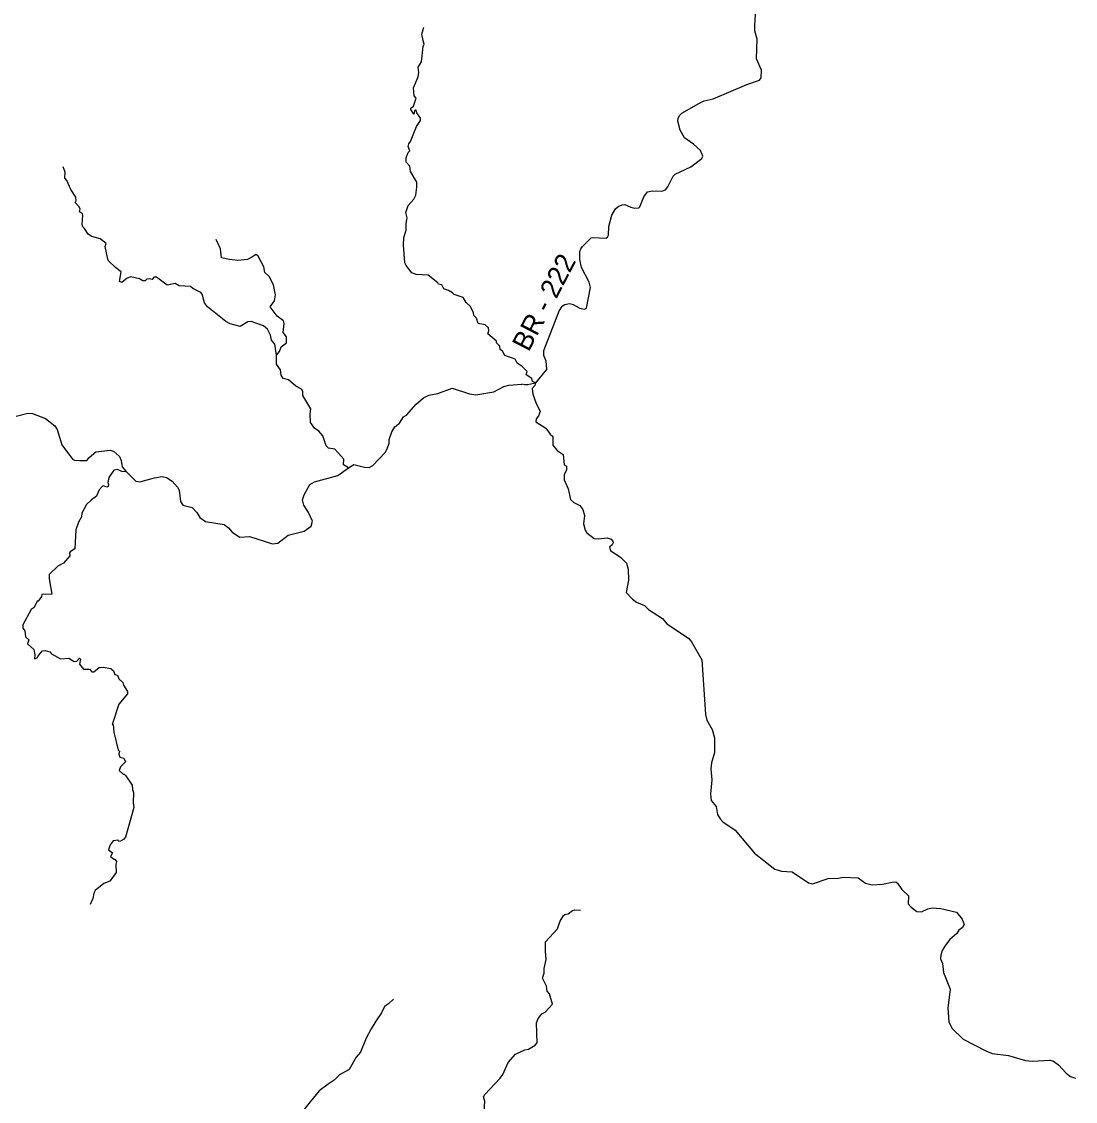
# Model space of a CAD drawing. Extents: x 332 to 501, y 9447 to 9559.
# Drawn here: x 378.21 to 398.6, y 9525.86 to 9546.74 of the extents above; entities that cross this region are included whole.
import ezdxf

# ---------------------------------------------------------------- set-up
doc = ezdxf.new("R2010")
doc.units = 0
for name, color, linetype in [('Level 2', 7, 'Continuous'), ('Level 31', 7, 'Continuous'), ('Level 5', 7, 'Continuous'), ('Level 6', 7, 'Continuous'), ('Level 7', 7, 'Continuous')]:
    doc.layers.add(name, color=color, linetype=linetype)

msp = doc.modelspace()

# ---------------------------------------------------------------- linework, layer by layer
at = {"layer": 'Level 2'}
for points in [[(389.0092, 9541.194), (389.1024, 9541.175), (389.1431, 9541.1966), (389.2215, 9541.5947), (389.1959, 9541.7003), (389.044, 9541.9801), (389.0152, 9542.1384), (389.0152, 9542.2919), (389.0296, 9542.3431), (389.0648, 9542.3878), (389.2311, 9542.5541), (389.2711, 9542.5637), (389.5148, 9542.5497), (389.5486, 9542.5649), (389.5683, 9542.6033), (389.5774, 9542.7724), (389.6301, 9542.9943), (389.7012, 9543.117), (389.7571, 9543.1633), (389.8307, 9543.1953), (389.8851, 9543.2001), (389.997, 9543.1457), (390.0769, 9543.1265), (390.1553, 9543.1345), (390.1761, 9543.1521), (390.2519, 9543.3458), (390.32, 9543.4431), (390.4127, 9543.4623), (390.6014, 9543.4543), (390.6676, 9543.4853), (390.7128, 9543.5383), (390.8204, 9543.7502), (390.8572, 9543.7885), (391.161, 9543.9276), (391.3705, 9544.0907), (391.3913, 9544.1371), (391.3481, 9544.2426), (391.2122, 9544.3689), (391.0411, 9544.4889), (390.9516, 9544.6392), (390.9084, 9544.8119), (390.9148, 9544.8694), (390.95, 9544.927), (390.9835, 9544.9638), (391.3145, 9545.1556), (391.4217, 9545.202), (391.5928, 9545.242), (392.2451, 9545.5186), (392.4866, 9545.6034), (392.5217, 9545.6481), (392.5249, 9545.8), (392.4306, 9546.0175), (392.4466, 9546.3981), (392.3999, 9546.5581), (392.3975, 9546.6618), (392.4258, 9547.076)], [(389.0092, 9541.194), (388.8937, 9541.2594), (388.8106, 9541.2767), (388.7205, 9541.2594), (388.6616, 9541.2178), (388.6131, 9541.152), (388.3117, 9540.3725), (388.3117, 9540.2859), (388.3568, 9540.1733), (388.3706, 9540.0104), (388.1558, 9539.7504)], [(384.5385, 9538.1042), (384.6403, 9538.1748), (384.846, 9538.1203), (384.9367, 9538.1143), (385.0093, 9538.1506), (385.2452, 9538.4048), (385.2876, 9538.4775), (385.3239, 9538.5864), (385.3239, 9538.653), (385.3783, 9538.8044), (385.4371, 9538.8988), (385.5218, 9538.9714), (385.6004, 9539.0925), (385.6609, 9539.1288), (385.8485, 9539.3407), (385.9876, 9539.4618), (386.0905, 9539.5102), (386.2659, 9539.5465), (386.5442, 9539.6494), (386.8769, 9539.5405), (387.004, 9539.5162), (387.3525, 9539.5768), (387.5401, 9539.6797), (387.6369, 9539.7039), (387.891, 9539.7221)], [(387.9483, 9539.7141), (387.891, 9539.7221)], [(388.0064, 9539.7127), (387.9483, 9539.7141)], [(388.1253, 9539.7402), (388.0064, 9539.7127)], [(388.1558, 9539.7504), (388.1253, 9539.7402)], [(378.1074, 9539.1058), (378.3373, 9539.1664), (378.422, 9539.1603), (378.6761, 9539.0635), (378.8552, 9538.9182), (378.9036, 9538.8516), (378.9944, 9538.555), (379.2001, 9538.2765), (379.2364, 9538.2583), (379.3392, 9538.2462), (379.4784, 9538.2462), (379.5207, 9538.3068), (379.6478, 9538.4157), (379.9261, 9538.446), (379.9926, 9538.4278), (380.1076, 9538.3249), (380.1378, 9538.2523), (380.156, 9538.1252), (380.2286, 9538.0404)], [(380.2286, 9538.0404), (380.4222, 9537.8528), (380.5008, 9537.8346), (380.7851, 9537.9133), (380.9303, 9537.9375), (381.015, 9537.9194), (381.1239, 9537.8467)], [(383.3727, 9536.8067), (383.6813, 9536.8854), (383.8144, 9536.9762), (383.8386, 9537.0731), (383.766, 9537.2426), (383.6723, 9537.3879), (383.6481, 9537.4908), (383.6783, 9537.5876), (383.7872, 9537.7874), (383.878, 9537.8358), (384.3317, 9537.9569), (384.5385, 9538.1042)], [(381.1239, 9537.8467), (381.2328, 9537.7317), (381.2631, 9537.6772), (381.2873, 9537.4532), (381.3357, 9537.3867), (381.5111, 9537.3382), (381.6019, 9537.2414), (381.6624, 9537.1445), (381.7713, 9537.0719), (382.1325, 9537.0126), (382.2172, 9536.946), (382.2898, 9536.8612), (382.435, 9536.7644), (382.6225, 9536.7765), (383.0702, 9536.6372), (383.1731, 9536.6493), (383.3727, 9536.8067)]]:
    msp.add_lwpolyline(points, dxfattribs=at)
at = {"layer": 'Level 5'}
for points in [[(386.0014, 9546.3018), (385.9838, 9546.3737), (385.9537, 9546.4941), (385.9938, 9546.6295)], [(385.6474, 9543.0433), (385.6908, 9543.1777), (385.8014, 9543.3041), (385.8409, 9543.3792), (385.8567, 9543.5333), (385.8567, 9543.6309), (385.7343, 9543.8364), (385.7224, 9543.9391), (385.6513, 9544.0182), (385.6553, 9544.1051), (385.6948, 9544.2039), (385.7224, 9544.2355), (385.6948, 9544.3224), (385.7027, 9544.3698), (385.7382, 9544.4197), (385.8527, 9544.7081), (385.9317, 9544.8267), (385.9278, 9544.8701), (385.8606, 9544.9689), (385.8448, 9545.0203), (385.833, 9545.0321), (385.8132, 9545.0084), (385.8014, 9544.9452), (385.7461, 9545.0361), (385.7461, 9545.0598), (385.7935, 9545.0993), (385.8448, 9545.2534), (385.8093, 9545.3008), (385.7974, 9545.4538), (385.8843, 9545.6711), (385.8962, 9545.7541), (385.8883, 9545.8529), (385.9475, 9545.9556), (385.9843, 9546.2575), (386.0014, 9546.3018)], [(379.3441, 9543.1068), (379.3289, 9543.1548), (379.2494, 9543.2376), (379.266, 9543.2741), (379.2627, 9543.3436), (379.1666, 9543.4894), (379.0871, 9543.6617), (379.0473, 9543.708), (379.0573, 9543.8273), (379.0208, 9543.9267)], [(380.0312, 9541.9799), (379.8966, 9542.1117), (379.8849, 9542.1408), (379.8296, 9542.3854), (379.85, 9542.4436), (379.735, 9542.5356), (379.5719, 9542.5822), (379.5021, 9542.6288), (379.4325, 9542.7355), (379.395, 9542.7667), (379.3825, 9542.8105), (379.395, 9542.9917), (379.3887, 9543.0167), (379.3325, 9543.0604), (379.3441, 9543.1068)], [(385.6513, 9542.0175), (385.6276, 9542.0728), (385.6, 9542.4126), (385.6079, 9542.5588), (385.6513, 9542.7011), (385.6513, 9542.8315), (385.6711, 9542.9445), (385.6474, 9543.0433)], [(383.1445, 9540.2829), (383.2028, 9540.3557), (383.2374, 9540.4444), (383.336, 9540.5234), (383.336, 9540.6417), (383.2768, 9540.7256), (383.2916, 9540.8982), (383.2818, 9540.9475), (383.1585, 9541.0413), (383.0598, 9541.1695), (383.0253, 9541.2188), (383.1042, 9541.3372), (383.1239, 9541.4556), (383.0845, 9541.6479), (383.0006, 9541.8058), (382.9168, 9541.8847), (382.902, 9541.9932), (382.8477, 9542.0919), (382.8477, 9542.0919), (382.7885, 9542.2004), (382.754, 9542.2349), (382.6702, 9542.1806), (382.5814, 9542.1362), (382.3939, 9542.1165), (382.2361, 9542.1362), (382.0783, 9542.1658), (382.0635, 9542.3434), (381.9796, 9542.5259)], [(381.8124, 9541.2189), (381.755, 9541.2954), (381.7072, 9541.4674), (381.6786, 9541.4961), (381.5257, 9541.5725), (381.4826, 9541.6155), (381.2628, 9541.6299), (381.1816, 9541.6729), (381.0287, 9541.6394), (380.8247, 9541.7916), (380.7722, 9541.7916), (380.7387, 9541.7486), (380.6909, 9541.7629), (380.6336, 9541.7534), (380.6049, 9541.7247), (380.5571, 9541.7247), (380.495, 9541.7629), (380.3278, 9541.8012), (380.2561, 9541.7725), (380.1557, 9541.6912), (380.1079, 9541.7104), (380.1388, 9541.8999), (380.0312, 9541.9799)], [(388.1558, 9539.7504), (388.1004, 9539.7745), (388.0865, 9539.8379), (387.9736, 9539.9033), (387.9974, 9539.9686), (387.8972, 9540.064), (387.7985, 9540.1312), (387.763, 9540.2062), (387.5616, 9540.2812), (387.5181, 9540.3641), (387.4707, 9540.3957), (387.4668, 9540.4589), (387.4036, 9540.5221), (387.4036, 9540.5576), (387.2338, 9540.6959), (387.2535, 9540.759), (387.2456, 9540.8143), (387.1825, 9540.8696), (387.0443, 9540.8973), (387.0166, 9541.0039), (386.9613, 9541.0553), (386.9574, 9541.1027), (386.8981, 9541.2252), (386.8113, 9541.3042), (386.756, 9541.399), (386.5822, 9541.4583), (386.5506, 9541.4939), (386.4717, 9541.5373), (386.3808, 9541.5689), (386.3414, 9541.644), (386.2821, 9541.6559), (386.2674, 9541.6856), (386.0778, 9541.8318), (385.8488, 9541.8476), (385.7659, 9541.8752), (385.6513, 9542.0175)], [(383.8813, 9538.8743), (383.8051, 9538.9854), (383.7934, 9539.1482), (383.8117, 9539.2481), (383.6553, 9539.5046), (383.6519, 9539.5863), (383.6286, 9539.6313), (383.5158, 9539.6871), (383.3743, 9539.8071), (383.2761, 9539.8371), (383.2328, 9539.902), (383.2228, 9540.0003), (383.1462, 9540.1097), (383.1445, 9540.2829), (383.1121, 9540.4974), (383.0452, 9540.5786), (383.0309, 9540.6742), (382.9736, 9540.7888), (382.8923, 9540.8557), (382.6534, 9540.937), (382.5913, 9540.9322), (382.4431, 9540.8414), (382.2472, 9540.894), (382.166, 9540.937), (381.8124, 9541.2189)], [(388.1558, 9539.7504), (388.1399, 9539.7013), (388.0932, 9539.6413), (388.1066, 9539.5348), (388.1617, 9539.3714), (388.2456, 9539.1975), (388.2156, 9539.1136), (388.1677, 9539.0566), (388.1647, 9538.9966), (388.3535, 9538.8718), (388.4375, 9538.7578), (388.4914, 9538.7158), (388.4914, 9538.5478), (388.5754, 9538.4458), (388.6923, 9538.3684), (388.7103, 9538.1674), (388.7552, 9538.1374), (388.7582, 9538.0684), (388.7103, 9537.9725), (388.7133, 9537.8765), (388.7852, 9537.7033), (388.8302, 9537.4964), (388.8991, 9537.4394), (389.0141, 9537.3772)], [(384.5385, 9538.1042), (384.4411, 9538.1646), (384.4453, 9538.2727), (384.2762, 9538.4676), (384.148, 9538.4876), (384.1064, 9538.5359), (384.0442, 9538.7239), (383.9616, 9538.8139), (383.8813, 9538.8743)], [(380.2286, 9538.0404), (380.2335, 9538.0274), (380.1557, 9538.0338), (380.0672, 9538.077), (379.9959, 9538.0619), (379.903, 9537.9215), (379.8836, 9537.8243), (379.8965, 9537.7898), (379.8879, 9537.7466), (379.8598, 9537.7358), (379.7972, 9537.7617), (379.7691, 9537.7466), (379.7151, 9537.6839), (379.6633, 9537.5565), (379.5661, 9537.4895), (379.4711, 9537.3967), (379.3803, 9537.2336), (379.3695, 9537.1602), (379.3134, 9537.0543), (379.2659, 9536.9073), (379.2421, 9536.5431), (379.1514, 9536.4826), (379.1384, 9536.4653), (379.1449, 9536.4048), (379.0261, 9536.2643), (378.9168, 9536.2038), (378.7461, 9536.0461), (378.7461, 9535.963), (378.798, 9535.6648), (378.6069, 9535.6606), (378.5982, 9535.6217), (378.5335, 9535.5309)], [(389.0141, 9537.3772), (389.0699, 9537.3012), (389.1047, 9537.1873), (389.0857, 9537.0243), (389.1143, 9536.9002), (389.1495, 9536.849), (389.2886, 9536.7387), (389.3766, 9536.7339), (389.5397, 9536.7547), (389.618, 9536.7307), (389.6516, 9536.6923), (389.658, 9536.6603), (389.6409, 9536.6205), (389.5844, 9536.574), (389.6036, 9536.51), (389.8051, 9536.3741), (389.9138, 9536.2638), (389.9458, 9536.1487), (389.9554, 9535.9328), (389.9069, 9535.6963)], [(378.5335, 9535.5309), (378.5162, 9535.5266), (378.4557, 9535.4056), (378.3995, 9535.371), (378.2397, 9535.0728), (378.2397, 9535.008), (378.2743, 9534.9561), (378.2916, 9534.8394), (378.3563, 9534.7832), (378.3261, 9534.7011), (378.4514, 9534.593), (378.4687, 9534.4893), (378.46, 9534.4158), (378.5162, 9534.4331), (378.5378, 9534.4806), (378.6198, 9534.5714), (378.6717, 9534.5757), (378.7581, 9534.5498), (378.7926, 9534.5109), (378.9654, 9534.4115), (379.1296, 9534.4245), (379.2332, 9534.3639), (379.2807, 9534.3683), (379.3369, 9534.4288), (379.3499, 9534.4072), (379.3369, 9534.3078), (379.4103, 9534.217), (379.527, 9534.2127), (379.5702, 9534.1608), (379.609, 9534.1608), (379.7127, 9534.2472), (379.7905, 9534.2559), (379.9416, 9534.2256), (379.9892, 9534.1824), (380.0151, 9534.1133), (380.0712, 9534.096), (380.0972, 9534.0268), (380.1706, 9533.9577), (380.1835, 9533.9058), (380.2613, 9533.7825), (380.2613, 9533.735), (380.0972, 9533.5405), (379.9676, 9533.1428), (379.9863, 9533.1462), (380, 9532.993), (380.0793, 9532.6456), (380.0957, 9532.6347)], [(380.0957, 9532.6347), (380.1094, 9532.6292), (380.0957, 9532.569), (380.1121, 9532.5116), (380.1887, 9532.4952), (380.2215, 9532.4213), (380.1285, 9532.3256), (380.1012, 9532.2545), (380.1778, 9532.1806), (380.1969, 9532.1834), (380.2325, 9532.1533), (380.3552, 9531.9726), (380.3586, 9531.8855), (380.3787, 9531.8285), (380.372, 9531.6308), (380.3854, 9531.5369), (380.2245, 9530.9672), (380.1843, 9530.9203), (380.124, 9530.8868), (380.0938, 9530.8834), (380.0804, 9530.9103), (379.9832, 9530.8969), (379.9296, 9530.8198), (379.8927, 9530.7226), (379.9698, 9530.6644), (379.933, 9530.5907), (380, 9530.537), (380.0201, 9530.537), (380.0502, 9530.4968), (380.0368, 9530.4465), (380.0435, 9530.2855), (379.9229, 9530.1179), (379.8056, 9530.0676), (379.638, 9529.9368), (379.6079, 9529.8831), (379.5911, 9529.7825), (379.5409, 9529.6652)], [(388.2804, 9527.5495), (388.3409, 9527.5797), (388.4872, 9527.7361), (388.4266, 9527.9379), (388.3813, 9527.9884), (388.3712, 9528.0842), (388.2905, 9528.2406), (388.3208, 9528.3365), (388.3208, 9528.4273), (388.3611, 9528.5988), (388.346, 9528.7603), (388.351, 9528.9419), (388.583, 9529.1942), (388.6283, 9529.3253), (388.6989, 9529.4515), (388.7241, 9529.4716), (388.7897, 9529.4817), (388.8704, 9529.5473), (388.9157, 9529.5625), (389.0242, 9529.556)], [(387.1621, 9525.6582), (387.1767, 9525.8586), (387.1514, 9525.9443), (387.1767, 9525.9897), (387.4691, 9526.3025), (387.5246, 9526.3782), (387.6254, 9526.6052), (387.7666, 9526.7717), (387.9481, 9526.8524), (388.0187, 9526.8676), (388.1498, 9526.9432), (388.1901, 9526.9887), (388.1745, 9527.3729), (388.2048, 9527.4587), (388.2804, 9527.5495)]]:
    msp.add_lwpolyline(points, dxfattribs=at)
at = {"layer": 'Level 6'}
for points in [[(389.9069, 9535.6963), (390.0343, 9535.5663)], [(390.0343, 9535.5663), (390.1069, 9535.5126), (390.2671, 9535.4461), (390.3418, 9535.3649), (390.6142, 9535.1909), (390.6973, 9535.0885), (391.1147, 9534.8119), (391.1722, 9534.7432), (391.3721, 9534.3978), (391.444, 9533.3345), (391.468, 9533.2273), (391.5704, 9533.0483), (391.6215, 9532.8836), (391.6215, 9532.6053), (391.5608, 9532.4007), (391.548, 9532.2855), (391.5672, 9532.0713), (391.5442, 9531.8009), (391.5544, 9531.6715), (391.6535, 9531.558), (391.6759, 9531.4029), (391.7271, 9531.3198), (391.783, 9531.2638), (392.0165, 9531.1007), (392.3906, 9530.6578), (392.7888, 9530.3444), (392.9167, 9530.306), (393.1182, 9530.298), (393.4348, 9530.0806), (393.5163, 9530.063), (393.8201, 9530.1669), (394.02, 9530.1701), (394.1079, 9530.1893), (394.3989, 9530.1781), (394.5381, 9530.0742), (394.6708, 9530.047), (394.8674, 9530.0566), (395.0529, 9530.0982), (395.1281, 9530.0998), (395.1617, 9530.0742), (395.2432, 9529.9559), (395.3695, 9529.8311), (395.3663, 9529.6744), (395.4239, 9529.6089), (395.5358, 9529.5273), (395.6222, 9529.5209), (395.7469, 9529.5801), (395.8268, 9529.5993), (395.9975, 9529.584), (396.3024, 9529.5171), (396.4072, 9529.3786), (396.4488, 9529.2747), (396.4136, 9529.2203), (396.3465, 9529.166), (396.3087, 9529.1002)], [(396.3087, 9529.1002), (396.1727, 9528.9846), (396.0905, 9528.8793), (396.0243, 9528.7757), (395.9963, 9528.6831)], [(395.9963, 9528.6831), (395.9931, 9528.6127), (396.0267, 9528.5232), (396.0459, 9528.3489), (396.1786, 9528.0291), (396.1306, 9527.6565), (396.153, 9527.3959), (396.2122, 9527.2696), (396.4264, 9527.0617), (396.8662, 9526.8347), (396.9934, 9526.7836)], [(385.4068, 9527.8345), (385.3149, 9527.7426), (385.2361, 9527.6901), (385.1792, 9527.5719), (385.0698, 9527.41), (384.9779, 9527.2612), (384.8772, 9527.0818), (384.7722, 9526.8061), (384.6847, 9526.7098), (384.549, 9526.4735), (384.3652, 9526.3685), (384.2602, 9526.2635), (384.142, 9526.1925), (384.142, 9526.1925), (383.9681, 9526.0572), (383.7975, 9525.8479), (383.5946, 9525.5935), (383.5837, 9525.5633)]]:
    msp.add_lwpolyline(points, dxfattribs=at)
at = {"layer": 'Level 7'}
msp.add_lwpolyline([(396.9934, 9526.7836), (397.3091, 9526.7467), (397.6385, 9526.646), (397.7664, 9526.6316), (398.1092, 9526.6558), (398.1789, 9526.6332), (398.2716, 9526.566), (398.4236, 9526.4029), (398.5067, 9526.339), (398.601, 9526.307)], dxfattribs=at)

# ---------------------------------------------------------------- texts
at = {"layer": 'Level 31'}
msp.add_text('BR - 222', height=0.38, rotation=62.47443, dxfattribs=at).set_placement((388.0228, 9540.3342))

doc.saveas('drawing.dxf')
